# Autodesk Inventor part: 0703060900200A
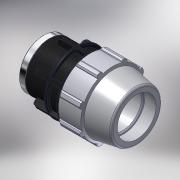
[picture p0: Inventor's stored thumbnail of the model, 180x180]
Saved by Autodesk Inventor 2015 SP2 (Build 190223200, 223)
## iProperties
Created: 2017-02
Part Number: 0703060900200A
Material: PVC-Piping
Description: PLASSON FEMALE ADAPTOR 90-2"
Document SubType Name: Modeling
Designer: KIM
Mass: 92.6774 g
Surface Area: 199.44 cm^2
Volume: 66.1981 cm^3
Density: 1.4 g/cm^3
Appearance: PTFE
Author: KIM
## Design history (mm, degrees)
derived "87030.ipt"
feature "Solid1::87030.ipt"
tag "TaggingFeature1"
body "Solid1"
other parameters: "d4" = 30.42857, "d5" = 53.25, "d7" = 154, "d9" = 30.42857, "d11" = 6.08571, "d12" = 123.2, "d13" = 120 deg, "d14" = 117, "d15" = 10 deg, "d16" = 138.6, "d18" = 4.5, "d19" = 35 deg, "d20" = 17.5 deg, "d21" = 143.22, "d23" = 0, "d25" = 360 deg, "d27" = 3.08, "d34" = 7.7, "d35" = 63.9, "d36" = 0, "d42" = 53.25, "d43" = 4.62, "d46" = 2.7, "d49" = 183, "d51" = 213, "d53" = 1.8, "d55" = 360 deg, "d62" = 72, "d63" = 56.656, "d64" = 71, "d65" = 7.7, "d69" = 110.88, "d70" = 3.85, "d71" = 12.6, "d72" = 0.5, "d73" = 1, "E_" = 154, "H_" = 213, "l_" = 183, "Rp_Rc_" = 56.656
